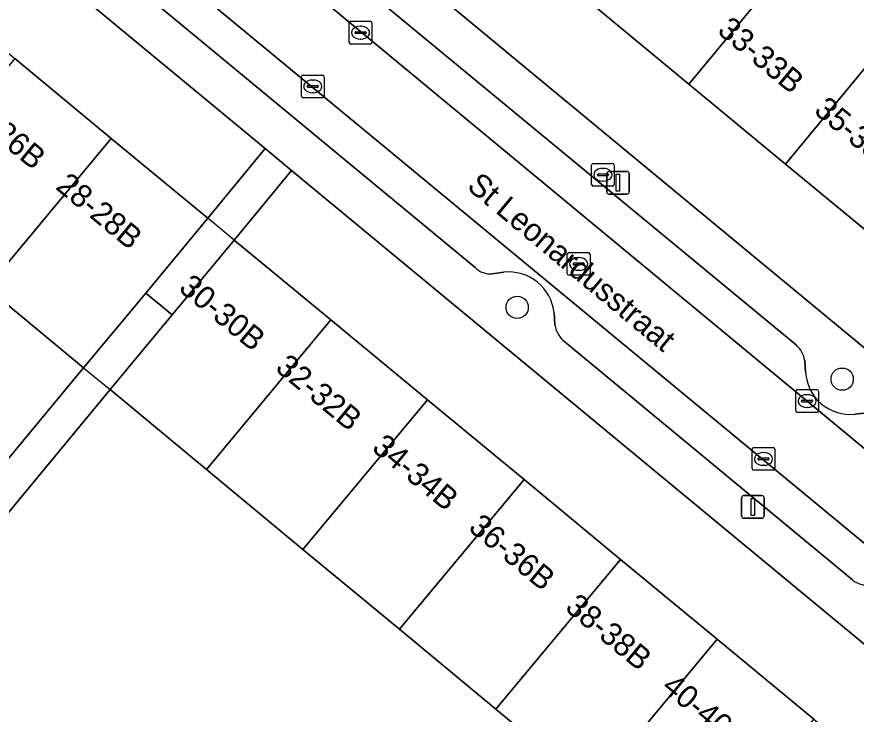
# Model space of a CAD drawing. Extents: x 162073 to 163043, y 381818 to 382561.
# Drawn here: x 162511.56 to 162548.47, y 382165.07 to 382195.73 of the extents above; entities that cross this region are included whole.
import ezdxf

# ---------------------------------------------------------------- set-up
doc = ezdxf.new("R2010")
doc.units = 0
for name, color, linetype in [('IMGEO_Boom', 7, 'Continuous'), ('IMGEO_Brandkraan', 7, 'Continuous'), ('IMGEO_Erf', 7, 'Continuous'), ('IMGEO_Kolk', 7, 'Continuous'), ('IMGEO_Lichtmast', 7, 'Continuous'), ('IMGEO_Openbare_ruimte_label', 7, 'Continuous'), ('IMGEO_Pand', 7, 'Continuous'), ('IMGEO_Pand_nummerreeks', 7, 'Continuous'), ('IMGEO_Pand_overbouw', 7, 'Continuous'), ('IMGEO_Parkeervlak_open', 7, 'Continuous'), ('IMGEO_Rijbaan_lokaal_open', 7, 'Continuous'), ('IMGEO_Rioolput', 7, 'Continuous'), ('IMGEO_Voetpad_open', 7, 'Continuous')]:
    doc.layers.add(name, color=color, linetype=linetype)

msp = doc.modelspace()

# ---------------------------------------------------------------- linework, layer by layer
at = {"layer": 'IMGEO_Boom'}
for centre in [(162533.564, 382182.955), (162547.858, 382179.8)]:
    msp.add_circle(centre, 0.489, dxfattribs=at)
at = {"layer": 'IMGEO_Brandkraan'}
for p, q in [((162536.91, 382189.286), (162537.762, 382189.286)), ((162536.835, 382188.36), (162536.835, 382189.212)), ((162537.323, 382189.066), (162537.348, 382189.066)), ((162537.836, 382189.212), (162537.836, 382188.36)), ((162537.094, 382188.78), (162537.094, 382188.792)), ((162537.532, 382188.743), (162537.134, 382188.743)), ((162537.137, 382188.829), (162537.535, 382188.829)), ((162537.346, 382188.506), (162537.321, 382188.506)), ((162537.578, 382188.792), (162537.578, 382188.78)), ((162537.762, 382188.286), (162536.91, 382188.286))]:
    msp.add_line(p, q, dxfattribs=at)
for points in [[(162536.91, 382189.286), (162537.762, 382189.286)], [(162536.835, 382188.36), (162536.835, 382189.212)], [(162537.836, 382189.212), (162537.836, 382188.36)], [(162537.762, 382188.286), (162536.91, 382188.286)]]:
    msp.add_lwpolyline(points, dxfattribs=at)
for centre, radius, start, end in [((162536.912, 382189.21), 0.0765, 91.552, 178.448), ((162536.912, 382189.21), 0.0765, 91.552, 178.448), ((162537.76, 382189.21), 0.0765, 1.552, 88.448), ((162537.76, 382189.21), 0.0765, 1.552, 88.448), ((162537.134, 382188.789), 0.0403, 85.8775, 175.7526), ((162537.131, 382188.779), 0.0366, 178.938, 274.7102), ((162537.535, 382188.786), 0.043, 264.8664, 352.4533), ((162537.539, 382188.791), 0.0386, 1.7309, 96.639), ((162536.912, 382188.362), 0.0765, 181.552, 268.448), ((162536.912, 382188.362), 0.0765, 181.552, 268.448), ((162537.76, 382188.362), 0.0765, 271.552, 358.448), ((162537.76, 382188.362), 0.0765, 271.552, 358.448)]:
    msp.add_arc(centre, radius, start, end, dxfattribs=at)
for centre, major_axis, ratio, start_param, end_param in [((162537.322, 382188.786), (-0.387, 0.002), 0.722429, 4.712389, 7.853982), ((162537.347, 382188.786), (-0.39, 0.002), 0.717154, 1.570796, 4.712389)]:
    msp.add_ellipse(centre, major_axis=major_axis, ratio=ratio, start_param=start_param, end_param=end_param, dxfattribs=at)
at = {"layer": 'IMGEO_Erf'}
for points in [[(162464.763, 382232.548), (162469.013, 382229.032), (162473.259, 382225.518), (162477.505, 382222.005), (162481.751, 382218.492), (162485.997, 382214.978), (162490.243, 382211.465), (162494.489, 382207.952), (162498.734, 382204.438), (162502.98, 382200.925), (162507.226, 382197.412), (162511.472, 382193.898), (162515.718, 382190.385), (162519.964, 382186.872), (162522.479, 382189.936), (162491.963, 382215.169), (162467.32, 382235.647)], [(162585.394, 382150.935), (162587.956, 382154.032), (162583.585, 382157.648), (162579.338, 382161.16), (162575.091, 382164.672), (162570.844, 382168.184), (162566.597, 382171.697), (162562.351, 382175.209), (162558.104, 382178.721), (162553.857, 382182.233), (162549.61, 382185.745), (162545.363, 382189.257), (162541.116, 382192.77), (162536.87, 382196.282), (162532.623, 382199.794), (162530.074, 382196.697)], [(162523.638, 382188.978), (162521.126, 382185.918), (162525.373, 382182.406), (162529.62, 382178.895), (162533.868, 382175.383), (162538.115, 382171.871), (162542.362, 382168.36), (162546.61, 382164.848), (162550.857, 382161.336), (162555.104, 382157.824), (162559.352, 382154.313), (162563.599, 382150.801), (162567.846, 382147.289), (162572.093, 382143.778), (162576.441, 382140.183), (162578.962, 382143.232)], [(162541.122, 382158.258), (162536.877, 382161.772), (162532.632, 382165.287), (162528.387, 382168.802), (162524.143, 382172.316), (162519.898, 382175.831), (162515.662, 382179.338), (162506.038, 382167.712), (162561.785, 382121.807), (162570.955, 382133.557), (162566.591, 382137.17), (162562.346, 382140.685), (162558.101, 382144.199), (162553.857, 382147.714), (162549.612, 382151.228), (162545.367, 382154.743)]]:
    msp.add_lwpolyline(points, close=True, dxfattribs=at)
msp.add_lwpolyline([(162504.869, 382168.675), (162514.495, 382180.304), (162510.25, 382183.819)], dxfattribs=at)
at = {"layer": 'IMGEO_Kolk'}
for p, q in [((162526.252, 382195.536), (162527.104, 382195.536)), ((162526.177, 382194.61), (162526.177, 382195.462)), ((162526.665, 382195.316), (162526.69, 382195.316)), ((162527.178, 382195.462), (162527.178, 382194.61)), ((162526.436, 382195.03), (162526.436, 382195.042)), ((162526.874, 382194.993), (162526.476, 382194.993)), ((162526.479, 382195.079), (162526.877, 382195.079)), ((162526.688, 382194.756), (162526.663, 382194.756)), ((162526.92, 382195.042), (162526.92, 382195.03)), ((162527.104, 382194.536), (162526.252, 382194.536)), ((162524.078, 382192.246), (162524.078, 382193.098)), ((162524.153, 382193.172), (162525.005, 382193.172)), ((162524.566, 382192.952), (162524.591, 382192.952)), ((162525.079, 382193.098), (162525.079, 382192.246)), ((162524.337, 382192.666), (162524.337, 382192.678)), ((162524.775, 382192.629), (162524.377, 382192.629)), ((162524.38, 382192.715), (162524.778, 382192.715)), ((162524.821, 382192.678), (162524.821, 382192.666)), ((162525.005, 382192.172), (162524.153, 382192.172)), ((162524.589, 382192.392), (162524.564, 382192.392)), ((162545.816, 382178.412), (162545.816, 382179.264)), ((162545.891, 382179.338), (162546.743, 382179.338)), ((162546.817, 382179.264), (162546.817, 382178.412)), ((162546.304, 382179.118), (162546.329, 382179.118)), ((162546.075, 382178.832), (162546.075, 382178.844)), ((162546.513, 382178.795), (162546.115, 382178.795)), ((162546.118, 382178.881), (162546.516, 382178.881)), ((162546.327, 382178.558), (162546.302, 382178.558)), ((162546.559, 382178.844), (162546.559, 382178.832)), ((162546.743, 382178.338), (162545.891, 382178.338)), ((162543.896, 382175.866), (162543.896, 382176.718)), ((162543.971, 382176.792), (162544.823, 382176.792)), ((162544.897, 382176.718), (162544.897, 382175.866)), ((162544.198, 382176.335), (162544.596, 382176.335)), ((162544.384, 382176.572), (162544.409, 382176.572)), ((162544.155, 382176.286), (162544.155, 382176.298)), ((162544.593, 382176.249), (162544.195, 382176.249)), ((162544.407, 382176.012), (162544.382, 382176.012)), ((162544.639, 382176.298), (162544.639, 382176.286)), ((162544.823, 382175.792), (162543.971, 382175.792))]:
    msp.add_line(p, q, dxfattribs=at)
for points in [[(162526.252, 382195.536), (162527.104, 382195.536)], [(162526.177, 382194.61), (162526.177, 382195.462)], [(162527.178, 382195.462), (162527.178, 382194.61)], [(162527.104, 382194.536), (162526.252, 382194.536)], [(162524.078, 382192.246), (162524.078, 382193.098)], [(162524.153, 382193.172), (162525.005, 382193.172)], [(162525.079, 382193.098), (162525.079, 382192.246)], [(162525.005, 382192.172), (162524.153, 382192.172)], [(162545.816, 382178.412), (162545.816, 382179.264)], [(162545.891, 382179.338), (162546.743, 382179.338)], [(162546.817, 382179.264), (162546.817, 382178.412)], [(162546.743, 382178.338), (162545.891, 382178.338)], [(162543.896, 382175.866), (162543.896, 382176.718)], [(162543.971, 382176.792), (162544.823, 382176.792)], [(162544.897, 382176.718), (162544.897, 382175.866)], [(162544.823, 382175.792), (162543.971, 382175.792)]]:
    msp.add_lwpolyline(points, dxfattribs=at)
for centre, radius, start, end in [((162526.254, 382195.46), 0.0765, 91.552, 178.448), ((162526.254, 382195.46), 0.0765, 91.552, 178.448), ((162527.102, 382195.46), 0.0765, 1.552, 88.448), ((162527.102, 382195.46), 0.0765, 1.552, 88.448), ((162526.476, 382195.039), 0.0403, 85.8775, 175.7526), ((162526.473, 382195.029), 0.0366, 178.938, 274.7102), ((162526.877, 382195.036), 0.043, 264.8664, 352.4533), ((162526.881, 382195.041), 0.0386, 1.7309, 96.639), ((162526.254, 382194.612), 0.0765, 181.552, 268.448), ((162526.254, 382194.612), 0.0765, 181.552, 268.448), ((162527.102, 382194.612), 0.0765, 271.552, 358.448), ((162527.102, 382194.612), 0.0765, 271.552, 358.448), ((162524.155, 382193.096), 0.0765, 91.552, 178.448), ((162524.155, 382193.096), 0.0765, 91.552, 178.448), ((162525.003, 382193.096), 0.0765, 1.552, 88.448), ((162525.003, 382193.096), 0.0765, 1.552, 88.448), ((162524.377, 382192.675), 0.0403, 85.8775, 175.7526), ((162524.374, 382192.665), 0.0366, 178.938, 274.7102), ((162524.778, 382192.672), 0.043, 264.8664, 352.4533), ((162524.782, 382192.677), 0.0386, 1.7309, 96.639), ((162524.155, 382192.248), 0.0765, 181.552, 268.448), ((162524.155, 382192.248), 0.0765, 181.552, 268.448), ((162525.003, 382192.248), 0.0765, 271.552, 358.448), ((162525.003, 382192.248), 0.0765, 271.552, 358.448), ((162545.893, 382179.262), 0.0765, 91.552, 178.448), ((162545.893, 382179.262), 0.0765, 91.552, 178.448), ((162546.741, 382179.262), 0.0765, 1.552, 88.448), ((162546.741, 382179.262), 0.0765, 1.552, 88.448), ((162546.115, 382178.841), 0.0403, 85.8775, 175.7526), ((162546.112, 382178.831), 0.0366, 178.938, 274.7102), ((162546.516, 382178.838), 0.043, 264.8664, 352.4533), ((162546.52, 382178.843), 0.0386, 1.7309, 96.639), ((162545.893, 382178.414), 0.0765, 181.552, 268.448), ((162545.893, 382178.414), 0.0765, 181.552, 268.448), ((162546.741, 382178.414), 0.0765, 271.552, 358.448), ((162546.741, 382178.414), 0.0765, 271.552, 358.448), ((162543.973, 382176.716), 0.0765, 91.552, 178.448), ((162543.973, 382176.716), 0.0765, 91.552, 178.448), ((162544.821, 382176.716), 0.0765, 1.552, 88.448), ((162544.821, 382176.716), 0.0765, 1.552, 88.448), ((162544.195, 382176.295), 0.0403, 85.8775, 175.7526), ((162544.6, 382176.297), 0.0386, 1.7309, 96.639), ((162544.192, 382176.285), 0.0366, 178.938, 274.7102), ((162544.596, 382176.292), 0.043, 264.8664, 352.4533), ((162543.973, 382175.868), 0.0765, 181.552, 268.448), ((162543.973, 382175.868), 0.0765, 181.552, 268.448), ((162544.821, 382175.868), 0.0765, 271.552, 358.448), ((162544.821, 382175.868), 0.0765, 271.552, 358.448)]:
    msp.add_arc(centre, radius, start, end, dxfattribs=at)
for centre, major_axis, ratio, start_param, end_param in [((162526.664, 382195.036), (-0.387, 0.002), 0.722429, 4.712389, 7.853982), ((162526.689, 382195.036), (-0.39, 0.002), 0.717154, 1.570796, 4.712389), ((162524.565, 382192.672), (-0.387, 0.002), 0.722429, 4.712389, 7.853982), ((162524.59, 382192.672), (-0.39, 0.002), 0.717154, 1.570796, 4.712389), ((162546.303, 382178.838), (-0.387, 0.002), 0.722429, 4.712389, 7.853982), ((162546.328, 382178.838), (-0.39, 0.002), 0.717154, 1.570796, 4.712389), ((162544.383, 382176.292), (-0.387, 0.002), 0.722429, 4.712389, 7.853982), ((162544.408, 382176.292), (-0.39, 0.002), 0.717154, 1.570796, 4.712389)]:
    msp.add_ellipse(centre, major_axis=major_axis, ratio=ratio, start_param=start_param, end_param=end_param, dxfattribs=at)
at = {"layer": 'IMGEO_Lichtmast'}
for p, q in [((162537.601, 382188.938), (162538.391, 382188.938)), ((162538.391, 382188.938), (162537.601, 382188.938)), ((162537.501, 382188.038), (162537.501, 382188.838)), ((162537.501, 382188.838), (162537.501, 382188.038)), ((162538.491, 382188.838), (162538.491, 382188.038)), ((162538.491, 382188.038), (162538.491, 382188.838)), ((162538.391, 382187.938), (162537.601, 382187.938)), ((162537.601, 382187.938), (162538.391, 382187.938)), ((162543.437, 382173.784), (162543.437, 382174.584)), ((162543.437, 382174.584), (162543.437, 382173.784)), ((162543.537, 382174.684), (162544.327, 382174.684)), ((162544.327, 382174.684), (162543.537, 382174.684)), ((162544.427, 382174.584), (162544.427, 382173.784)), ((162544.427, 382173.784), (162544.427, 382174.584)), ((162544.327, 382173.684), (162543.537, 382173.684)), ((162543.537, 382173.684), (162544.327, 382173.684))]:
    msp.add_line(p, q, dxfattribs=at)
for points in [[(162537.921, 382188.813), (162538.071, 382188.813), (162538.071, 382188.063), (162537.921, 382188.063), (162537.921, 382188.813)], [(162543.857, 382174.559), (162544.007, 382174.559), (162544.007, 382173.809), (162543.857, 382173.809), (162543.857, 382174.559)]]:
    msp.add_lwpolyline(points, dxfattribs=at)
for centre, start, end in [((162537.601, 382188.838), 90, 180), ((162537.601, 382188.838), 90, 180), ((162538.391, 382188.838), 0, 90), ((162538.391, 382188.838), 360, 90), ((162537.601, 382188.038), 180, 270), ((162537.601, 382188.038), 180, 270), ((162538.391, 382188.038), 270, 0), ((162538.391, 382188.038), 270, 0), ((162543.537, 382174.584), 90, 180), ((162543.537, 382174.584), 90, 180), ((162544.327, 382174.584), 0, 90), ((162544.327, 382174.584), 360, 90), ((162543.537, 382173.784), 180, 270), ((162543.537, 382173.784), 180, 270), ((162544.327, 382173.784), 270, 0), ((162544.327, 382173.784), 270, 0)]:
    msp.add_arc(centre, 0.1, start, end, dxfattribs=at)
at = {"layer": 'IMGEO_Pand'}
for points in [[(162546.555, 382199.341), (162544.28, 382201.223), (162543.981, 382201.47), (162542.367, 382202.925), (162536.87, 382196.282), (162541.116, 382192.77)], [(162541.116, 382192.77), (162545.363, 382189.257), (162550.802, 382195.829), (162546.555, 382199.341)], [(162545.363, 382189.257), (162549.61, 382185.745), (162555.049, 382192.317), (162550.802, 382195.829)], [(162510.25, 382183.819), (162515.718, 382190.385), (162511.472, 382193.898), (162506.005, 382187.333)], [(162510.25, 382183.819), (162514.495, 382180.304), (162517.23, 382183.588), (162519.964, 382186.872), (162515.718, 382190.385)], [(162519.898, 382175.831), (162525.373, 382182.406), (162521.126, 382185.918), (162518.394, 382182.628), (162515.662, 382179.338)], [(162519.898, 382175.831), (162524.143, 382172.316), (162529.62, 382178.895), (162525.373, 382182.406)], [(162533.868, 382175.383), (162529.62, 382178.895), (162524.143, 382172.316), (162528.387, 382168.802)], [(162533.868, 382175.383), (162528.387, 382168.802), (162532.632, 382165.287), (162538.115, 382171.871)], [(162542.362, 382168.36), (162538.115, 382171.871), (162532.632, 382165.287), (162536.877, 382161.772)], [(162542.362, 382168.36), (162536.877, 382161.772), (162541.122, 382158.258), (162546.61, 382164.848)]]:
    msp.add_lwpolyline(points, close=True, dxfattribs=at)
at = {"layer": 'IMGEO_Pand_overbouw'}
for points in [[(162521.126, 382185.918), (162519.964, 382186.872), (162517.23, 382183.588), (162518.394, 382182.628)], [(162517.23, 382183.588), (162514.495, 382180.304), (162515.662, 382179.338), (162518.394, 382182.628)]]:
    msp.add_lwpolyline(points, close=True, dxfattribs=at)
at = {"layer": 'IMGEO_Parkeervlak_open'}
for points in [[(162455.575, 382254.047), (162467.743, 382243.863), (162583.48, 382148.075)], [(162576.743, 382149.513), (162505.451, 382208.42), (162453.427, 382251.529)], [(162491.402, 382218.04), (162531.722, 382184.707)], [(162545.842, 382181.297), (162520.738, 382202.038)], [(162532.47, 382184.432), (162532.975, 382184.501)], [(162535.185, 382182.71), (162535.225, 382182.183)], [(162535.584, 382181.505), (162548.315, 382170.969)], [(162546.247, 382180.102), (162546.21, 382180.613)], [(162548.954, 382178.32), (162548.422, 382178.263)]]:
    msp.add_lwpolyline(points, dxfattribs=at)
for centre, radius, start, end in [((162532.385, 382185.355), 0.927, 224.3576, 275.2708), ((162533.195, 382182.513), 2, 5.6431, 96.3137), ((162536.393, 382182.367), 1.182, 188.9652, 226.8371), ((162545.099, 382180.456), 1.122, 8.0301, 48.5315), ((162548.202, 382180.208), 1.957, 183.1035, 276.4664), ((162548.934, 382171.734), 0.985, 231.0272, 277.8069)]:
    msp.add_arc(centre, radius, start, end, dxfattribs=at)
at = {"layer": 'IMGEO_Rijbaan_lokaal_open'}
msp.add_lwpolyline([(162599.371, 382134.967), (162586.579, 382145.506), (162586.493, 382145.572), (162583.59, 382147.984), (162583.48, 382148.075), (162467.743, 382243.863), (162455.575, 382254.047), (162453.427, 382251.529), (162505.451, 382208.42), (162576.743, 382149.513), (162581.599, 382145.482), (162584.507, 382143.092), (162586.648, 382141.318), (162597.298, 382132.492)], close=True, dxfattribs=at)
at = {"layer": 'IMGEO_Rioolput'}
for p, q in [((162535.77, 382184.441), (162535.77, 382185.293)), ((162535.845, 382185.367), (162536.697, 382185.367)), ((162536.771, 382185.293), (162536.771, 382184.441)), ((162536.029, 382184.861), (162536.029, 382184.873)), ((162536.467, 382184.824), (162536.069, 382184.824)), ((162536.072, 382184.91), (162536.47, 382184.91)), ((162536.258, 382185.147), (162536.283, 382185.147)), ((162536.513, 382184.873), (162536.513, 382184.861)), ((162536.281, 382184.587), (162536.256, 382184.587)), ((162536.697, 382184.367), (162535.845, 382184.367))]:
    msp.add_line(p, q, dxfattribs=at)
for points in [[(162535.77, 382184.441), (162535.77, 382185.293)], [(162535.845, 382185.367), (162536.697, 382185.367)], [(162536.771, 382185.293), (162536.771, 382184.441)], [(162536.697, 382184.367), (162535.845, 382184.367)]]:
    msp.add_lwpolyline(points, dxfattribs=at)
for centre, radius, start, end in [((162535.847, 382185.291), 0.0765, 91.552, 178.448), ((162535.847, 382185.291), 0.0765, 91.552, 178.448), ((162536.695, 382185.291), 0.0765, 1.552, 88.448), ((162536.695, 382185.291), 0.0765, 1.552, 88.448), ((162536.069, 382184.87), 0.0403, 85.8775, 175.7526), ((162536.066, 382184.86), 0.0366, 178.938, 274.7102), ((162536.47, 382184.867), 0.043, 264.8664, 352.4533), ((162536.474, 382184.872), 0.0386, 1.7309, 96.639), ((162535.847, 382184.443), 0.0765, 181.552, 268.448), ((162535.847, 382184.443), 0.0765, 181.552, 268.448), ((162536.695, 382184.443), 0.0765, 271.552, 358.448), ((162536.695, 382184.443), 0.0765, 271.552, 358.448)]:
    msp.add_arc(centre, radius, start, end, dxfattribs=at)
for centre, major_axis, ratio, start_param, end_param in [((162536.257, 382184.867), (-0.387, 0.002), 0.722429, 4.712389, 7.853982), ((162536.282, 382184.867), (-0.39, 0.002), 0.717154, 1.570796, 4.712389)]:
    msp.add_ellipse(centre, major_axis=major_axis, ratio=ratio, start_param=start_param, end_param=end_param, dxfattribs=at)
at = {"layer": 'IMGEO_Voetpad_open'}
for points in [[(162453.427, 382251.529), (162452.002, 382252.727), (162449.526, 382250.362), (162465.927, 382236.819), (162467.32, 382235.647), (162491.963, 382215.169), (162522.479, 382189.936), (162523.638, 382188.978), (162578.962, 382143.232), (162580.273, 382142.148), (162578.638, 382140.471), (162580.943, 382138.549), (162581.857, 382139.648), (162588.643, 382133.909), (162591.826, 382131.301), (162594.946, 382128.72), (162597.674, 382126.473), (162599.157, 382123.241)], [(162531.722, 382184.707), (162491.402, 382218.04)], [(162561.785, 382121.807), (162506.038, 382167.712), (162515.662, 382179.338), (162518.394, 382182.628), (162521.126, 382185.918), (162523.638, 382188.978), (162522.479, 382189.936), (162519.964, 382186.872), (162517.23, 382183.588), (162514.495, 382180.304), (162504.869, 382168.675), (162449.979, 382213.874), (162449.439, 382213.218), (162457.82, 382206.316), (162466.328, 382199.311), (162474.834, 382192.306), (162483.342, 382185.3), (162492.233, 382177.98), (162501.052, 382170.717), (162510.617, 382162.841)], [(162520.738, 382202.038), (162545.842, 382181.297)], [(162608.683, 382134.916), (162605.45, 382135.683), (162602.791, 382137.875), (162596.289, 382143.28), (162589.673, 382148.769), (162587.149, 382150.868), (162587.088, 382150.899), (162586.457, 382150.056), (162585.394, 382150.935), (162530.074, 382196.697)], [(162532.975, 382184.501), (162532.47, 382184.432)], [(162535.225, 382182.183), (162535.185, 382182.71)], [(162548.315, 382170.969), (162535.584, 382181.505)], [(162546.21, 382180.613), (162546.247, 382180.102)], [(162548.422, 382178.263), (162548.954, 382178.32)]]:
    msp.add_lwpolyline(points, dxfattribs=at)
for centre, radius, start, end in [((162532.385, 382185.355), 0.927, 224.3576, 275.2708), ((162533.195, 382182.513), 2, 5.6431, 96.3137), ((162536.393, 382182.367), 1.182, 188.9652, 226.8371), ((162545.099, 382180.456), 1.122, 8.0301, 48.5315), ((162548.202, 382180.208), 1.957, 183.1035, 276.4664), ((162548.934, 382171.734), 0.985, 231.0272, 277.8069)]:
    msp.add_arc(centre, radius, start, end, dxfattribs=at)

# ---------------------------------------------------------------- texts
at = {"layer": 'IMGEO_Openbare_ruimte_label'}
msp.add_text('St Leonardusstraat', height=1, rotation=320.1944, dxfattribs=at).set_placement((162531.309, 382188.198))
at = {"layer": 'IMGEO_Pand_nummerreeks'}
for s, rotation, p in [('33-33B', 320.4088, (162542.319, 382195.045)), ('26-26B', 320.3939, (162508.978, 382191.705)), ('35-35B', 320.4088, (162546.566, 382191.533)), ('28-28B', 320.3914, (162513.224, 382188.192)), ('30-30B', 320.4143, (162518.633, 382183.723)), ('32-32B', 320.4159, (162522.88, 382180.212)), ('34-34B', 320.4159, (162527.127, 382176.7)), ('36-36B', 320.4159, (162531.374, 382173.188)), ('38-38B', 320.4159, (162535.622, 382169.677)), ('40-40B', 320.4159, (162539.869, 382166.165))]:
    msp.add_text(s, height=1, rotation=rotation, dxfattribs=at).set_placement(p)

doc.saveas('drawing.dxf')
